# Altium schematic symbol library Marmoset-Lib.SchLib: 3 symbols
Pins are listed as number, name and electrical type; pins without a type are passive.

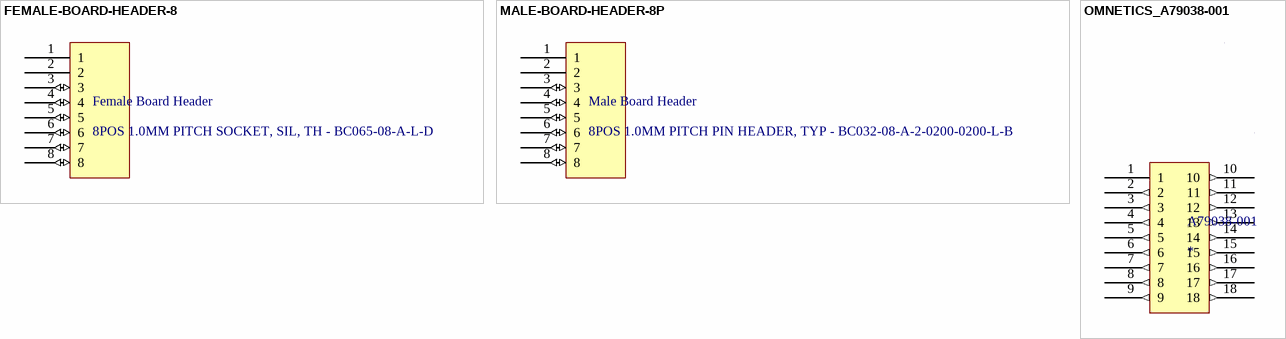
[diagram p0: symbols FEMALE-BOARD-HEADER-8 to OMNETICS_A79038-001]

## FEMALE-BOARD-HEADER-8
designator Female Board Header, comment 8POS 1.0MM PITCH SOCKET, SIL, TH - BC065-08-A-L-D
footprint FEMALE-BOARD-HEADER-8
footprint FEMALE-BOARD-HEADER-8
pins: 1 (power), 2 (power), 3 (io), 4 (io), 5 (io), 6 (io), 7 (io), 8 (io)

## MALE-BOARD-HEADER-8P
designator Male Board Header, comment 8POS 1.0MM PITCH PIN HEADER, TYP - BC032-08-A-2-0200-0200-L-B
footprint MALE-BOARD-HEADER-8
footprint MALE-BOARD-HEADER-8
pins: 1 (power), 2 (power), 3 (io), 4 (io), 5 (io), 6 (io), 7 (io), 8 (io)

## OMNETICS_A79038-001
designator A79038-001
18 PIN FEMALE NANO DUAL ROW CONNECTOR W/GUIDE POST HOLES
footprint OMNETICS_A79038-001_Footprint
pins: 1 (power), 2 (out), 3 (out), 4 (out), 5 (out), 6 (out), 7 (out), 8 (out), 9 (out), 10 (out), 11 (out), 12 (out), 13 (out), 14 (out), 15 (out), 16 (out), 17 (out), 18 (out)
